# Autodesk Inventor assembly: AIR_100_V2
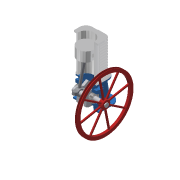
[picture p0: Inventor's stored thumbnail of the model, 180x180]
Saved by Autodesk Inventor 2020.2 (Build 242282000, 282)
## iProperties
Created: 2014-10
Part Number: AIR_100_V2
Document SubType Name: Assembly
Designer: F.Stasiak
Catalog Web Link: www.expertbooks.pl
Manager: www.cadconsulting.pl
Company: Fabian Stasiak CAD Consulting
Author: F.Stasiak
Subject: Zbiór ćwiczeń. Autodesk Inventor 2020. Kurs Professional
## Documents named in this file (11)
- C:\2020_Kurs_Professional\R3 Dynamika\AIR_100_V2.iam
- C:\2020_Kurs_Professional\R3 Dynamika\Komponenty_dyn\Korpus_AIR_01.ipt
- C:\2020_Kurs_Professional\R3 Dynamika\Komponenty_dyn\Wał_AIR_100.ipt
- C:\2020_Kurs_Professional\R3 Dynamika\Komponenty_dyn\Korbowód_AIR_100.ipt
- C:\2020_Kurs_Professional\R3 Dynamika\Komponenty_dyn\Cylinder_AIR_100.ipt
- C:\2020_Kurs_Professional\R3 Dynamika\Komponenty_dyn\Koło_AIR_100.ipt
- C:\2020_Kurs_Professional\R3 Dynamika\AIR_100\Design Accelerator\Łożysko2.iam
- C:\2020_Kurs_Professional\R3 Dynamika\AIR_100\Design Accelerator\Łożysko3.iam
- C:\2020_Kurs_Professional\R3 Dynamika\Komponenty_dyn\Sworzeń_AIR_100.ipt
- C:\2020_Kurs_Professional\R3 Dynamika\Komponenty_dyn\Stopka_AIR_100.ipt
- C:\2020_Kurs_Professional\R3 Dynamika\Komponenty_dyn\Tłok_AIR_100.ipt
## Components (10 placed, 9 different names)
1. Korpus_AIR_01:1
2. Cylinder_AIR_100:1 — Zestawiający:2, Zestawiający:9
3. Wał_AIR_100:1 — Wstaw:3, Zestawiający:6, Zestawiający:7, Równoległy:2, Wstaw:4
4. Korbowód_AIR_100:1 — Wstaw:1, Wstaw:2, Zestawiający:5, Wstaw:4
5. Stopka_AIR_100:1 — Wstaw:1, Wstaw:2
6. Sworzeń_AIR_100:1 — Równoległy:1, Zestawiający:5, Zestawiający:10, Zestawiający:11
7. Tłok_AIR_100:1 — Równoległy:1, Zestawiający:2, Zestawiający:9, Zestawiający:10, Zestawiający:11
8. Koło_AIR_100:1 — Zestawiający:6, Zestawiający:7, Równoległy:2
9. Łożysko:1 [sub-assembly]
10. Łożysko:2 [sub-assembly] — Wstaw:3
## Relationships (13: Mate 7, Insert 4, Flush 2)
- Wstaw:1 [Insert]: Korbowód_AIR_100:1 ↔ Stopka_AIR_100:1
- Wstaw:2 [Insert]: Korbowód_AIR_100:1 ↔ Stopka_AIR_100:1
- Równoległy:1 [Flush]: Sworzeń_AIR_100:1 ↔ Tłok_AIR_100:1
- Wstaw:3 [Insert]: Wał_AIR_100:1 ↔ Łożysko:2
- Zestawiający:2 [Mate]: Cylinder_AIR_100:1 ↔ Tłok_AIR_100:1
- Zestawiający:5 [Mate]: Korbowód_AIR_100:1 ↔ Sworzeń_AIR_100:1
- Zestawiający:6 [Mate]: Wał_AIR_100:1 ↔ Koło_AIR_100:1
- Zestawiający:7 [Mate]: Wał_AIR_100:1 ↔ Koło_AIR_100:1
- Równoległy:2 [Flush]: Wał_AIR_100:1 ↔ Koło_AIR_100:1
- Zestawiający:9 [Mate]: Cylinder_AIR_100:1 ↔ Tłok_AIR_100:1
- Wstaw:4 [Insert]: Wał_AIR_100:1 ↔ Korbowód_AIR_100:1
- Zestawiający:10 [Mate]: Sworzeń_AIR_100:1 ↔ Tłok_AIR_100:1
- Zestawiający:11 [Mate]: Sworzeń_AIR_100:1 ↔ Tłok_AIR_100:1
